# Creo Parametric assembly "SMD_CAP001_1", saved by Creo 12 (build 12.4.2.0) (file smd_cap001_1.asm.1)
Units: Custom; MM, KILOGRAM, SECS

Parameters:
  PTC_WM_ITERATION = "0"
  PTC_WM_VERSION = "-.0"
  PTC_WM_LIFECYCLE_STATE = "In Work"
  PTC_WM_LIFECYCLE = "MO_CADDocument"
  PTC_WM_CREATED_BY = "Maximilian Roepper (Z0017RMS: MO)"
  PTC_WM_CREATED_ON = "18-Sep-26 11:36:42 AM"
  PTC_WM_MODIFIED_BY = "Maximilian Roepper (Z0017RMS: MO)"
  PTC_WM_MODIFIED_ON = "18-Sep-26 11:36:46 AM"
  PDMLINKNUMBER = "PDM000071455081"
  PTC_WM_NUMBER = "PDM000071455081"

Other parameters: WEIGHT, WEIGHT_FACTOR, WEIGHT_ADD, MC_ERRORS, SUPPLIER

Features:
  1. coordinate system
  2. imported feature
  3. component "BODY008_1"
  4. component "CONTACT026_1"
  5. component "CONTACT027_1"

Other named items: DRW_VIEW_ORG, ROUGH-GROB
